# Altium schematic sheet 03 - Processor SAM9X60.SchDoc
size B; CompanyName: Microchip Technology Inc.; Organization: Microchip Technology; Address1: 2355 West Chandler Blvd.; Address2: Chandler, AZ  85224; Address4: USA; DocumentNumber: 3; SheetNumber: 3; SheetTotal: 13; SheetTitle: Processor SAM9X60
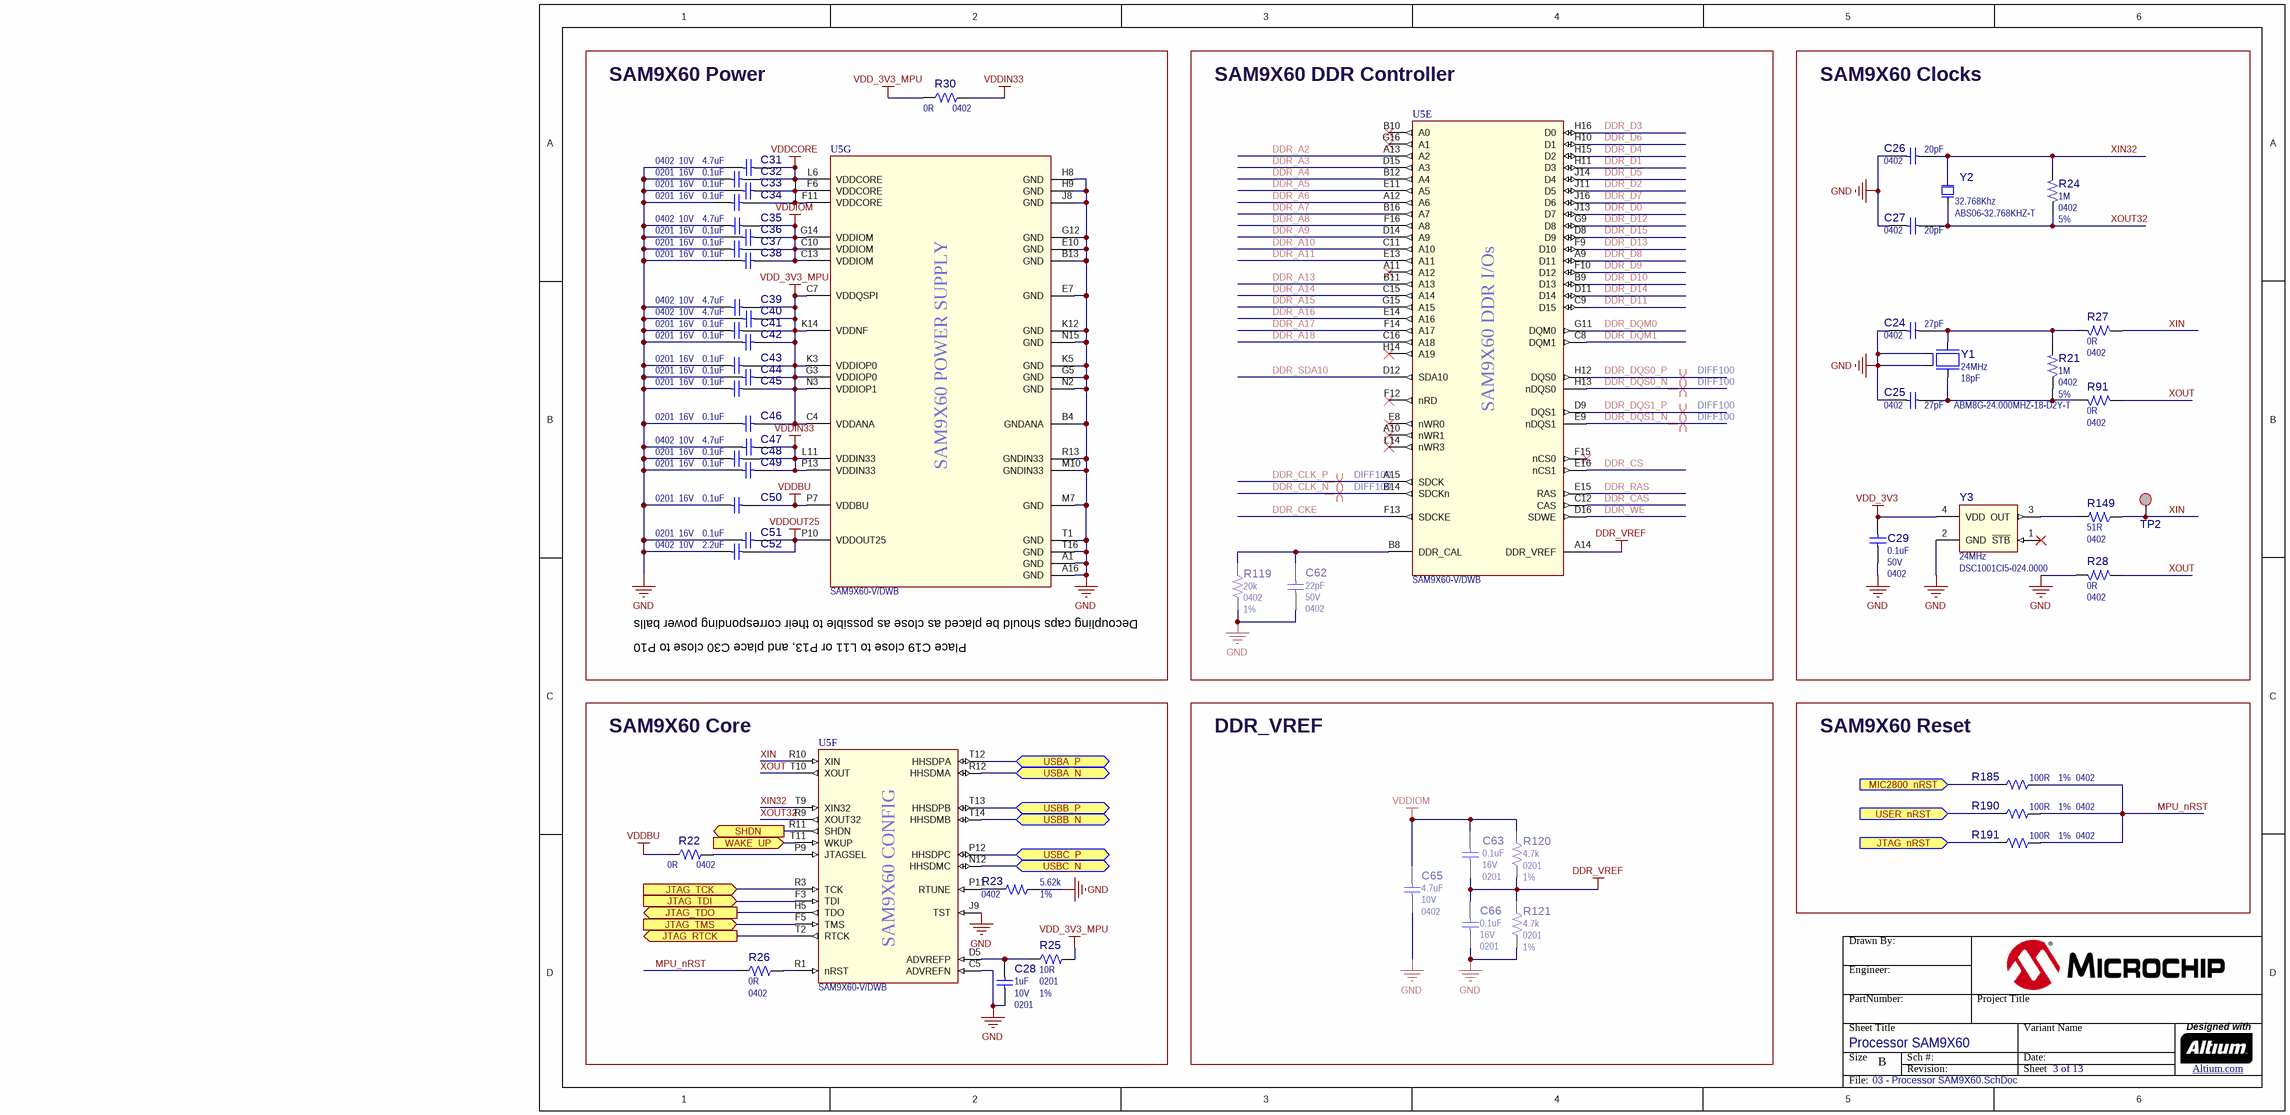
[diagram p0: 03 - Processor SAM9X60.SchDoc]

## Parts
?  (no value)  (graphical)
C24  value 27pF  Package: 0402  [CAP_C_0402]  (hidden comment: Capacitor NP)
C25  value 27pF  Package: 0402  [CAP_C_0402]  (hidden comment: Capacitor NP)
C26  value 20pF  Package: 0402  [CAP_C_0402]  (hidden comment: Capacitor NP)
C27  value 20pF  Package: 0402  [CAP_C_0402]  (hidden comment: Capacitor NP)
C28  value 1uF  Voltage: 10V  Package: 0201  [CAP_C_0201]  (hidden comment: Capacitor NP)
C29  value 0.1uF  Voltage: 50V  Package: 0402  [CAP_C_0402]  (hidden comment: Capacitor NP)
C31  value 4.7uF  Voltage: 10V  Package: 0402  [CAP_C_0402]  (hidden comment: Capacitor NP)
C32  value 0.1uF  Voltage: 16V  Package: 0201  [CAP_C_0201]  (hidden comment: Capacitor NP)
C33  value 0.1uF  Voltage: 16V  Package: 0201  [CAP_C_0201]  (hidden comment: Capacitor NP)
C34  value 0.1uF  Voltage: 16V  Package: 0201  [CAP_C_0201]  (hidden comment: Capacitor NP)
C35  value 4.7uF  Voltage: 10V  Package: 0402  [CAP_C_0402]  (hidden comment: Capacitor NP)
C36  value 0.1uF  Voltage: 16V  Package: 0201  [CAP_C_0201]  (hidden comment: Capacitor NP)
C37  value 0.1uF  Voltage: 16V  Package: 0201  [CAP_C_0201]  (hidden comment: Capacitor NP)
C38  value 0.1uF  Voltage: 16V  Package: 0201  [CAP_C_0201]  (hidden comment: Capacitor NP)
C39  value 4.7uF  Voltage: 10V  Package: 0402  [CAP_C_0402]  (hidden comment: Capacitor NP)
C40  value 4.7uF  Voltage: 10V  Package: 0402  [CAP_C_0402]  (hidden comment: Capacitor NP)
C41  value 0.1uF  Voltage: 16V  Package: 0201  [CAP_C_0201]  (hidden comment: Capacitor NP)
C42  value 0.1uF  Voltage: 16V  Package: 0201  [CAP_C_0201]  (hidden comment: Capacitor NP)
C43  value 0.1uF  Voltage: 16V  Package: 0201  [CAP_C_0201]  (hidden comment: Capacitor NP)
C44  value 0.1uF  Voltage: 16V  Package: 0201  [CAP_C_0201]  (hidden comment: Capacitor NP)
C45  value 0.1uF  Voltage: 16V  Package: 0201  [CAP_C_0201]  (hidden comment: Capacitor NP)
C46  value 0.1uF  Voltage: 16V  Package: 0201  [CAP_C_0201]  (hidden comment: Capacitor NP)
C47  value 4.7uF  Voltage: 10V  Package: 0402  [CAP_C_0402]  (hidden comment: Capacitor NP)
C48  value 0.1uF  Voltage: 16V  Package: 0201  [CAP_C_0201]  (hidden comment: Capacitor NP)
C49  value 0.1uF  Voltage: 16V  Package: 0201  [CAP_C_0201]  (hidden comment: Capacitor NP)
C50  value 0.1uF  Voltage: 16V  Package: 0201  [CAP_C_0201]  (hidden comment: Capacitor NP)
C51  value 0.1uF  Voltage: 16V  Package: 0201  [CAP_C_0201]  (hidden comment: Capacitor NP)
C52  value 2.2uF  Voltage: 10V  Package: 0402  [CAP_C_0402]  (hidden comment: Capacitor NP)
C62  value 22pF  Voltage: 50V  Package: 0402  [CAP_C_0402]  (hidden comment: Capacitor NP)
C63  value 0.1uF  Voltage: 16V  Package: 0201  [CAP_C_0201]  (hidden comment: Capacitor NP)
C65  value 4.7uF  Voltage: 10V  Package: 0402  [CAP_C_0402]  (hidden comment: Capacitor NP)
C66  value 0.1uF  Voltage: 16V  Package: 0201  [CAP_C_0201]  (hidden comment: Capacitor NP)
R21  value 1M  Package: 0402  Tolerance: 5%  [RES_C_0402]  (hidden comment: Resistor)
R22  value 0R  Package: 0402  [RES_C_0402]  (hidden comment: Resistor)
R23  value 5.62k  Package: 0402  Tolerance: 1%  [RES_C_0402]  (hidden comment: Resistor)
R24  value 1M  Package: 0402  Tolerance: 5%  [RES_C_0402]  (hidden comment: Resistor)
R25  value 10R  Package: 0201  Tolerance: 1%  [RES_C_0201]  (hidden comment: Resistor)
R26  value 0R  Package: 0402  [RES_C_0402]  (hidden comment: Resistor)
R27  value 0R  Package: 0402  [RES_C_0402]  (hidden comment: Resistor)
R28  value 0R  Package: 0402  [RES_C_0402]  (hidden comment: Resistor)
R30  value 0R  Package: 0402  [RES_C_0402]  (hidden comment: Resistor)
R91  value 0R  Package: 0402  [RES_C_0402]  (hidden comment: Resistor)
R119  value 20k  Package: 0402  Tolerance: 1%  [RES_C_0402]  (hidden comment: Resistor)
R120  value 4.7k  Package: 0201  Tolerance: 1%  [RES_C_0201]  (hidden comment: Resistor)
R121  value 4.7k  Package: 0201  Tolerance: 1%  [RES_C_0201]  (hidden comment: Resistor)
R149  value 51R  Package: 0402  [RES_C_0402]  (hidden comment: Resistor)
R185  value 100R  Package: 0402  Tolerance: 1%  [RES_C_0402]  (hidden comment: Resistor)
R190  value 100R  Package: 0402  Tolerance: 1%  [RES_C_0402]  (hidden comment: Resistor)
R191  value 100R  Package: 0402  Tolerance: 1%  [RES_C_0402]  (hidden comment: Resistor)
TP2  SMD Test Point  [TP_1x1_SMD]  (value not drawn)  (no BOM)
U5  value SAM9X60-V/DWB  [SAM9X60 TFBGA-228]  (hidden comment: SAM9X60 TFBGA-228)  (parts E,F,G of 7)
Y1  value 24MHz  Load Capacitance: 18pF  Manufacturer Part Number 1: ABM8G-24.000MHZ-18-D2Y-T  [CRYSTAL_ABM8G]  (hidden comment: Crystal 4 Pins)
Y2  value 32.768Khz  Manufacturer Part Number 1: ABS06-32.768KHZ-T  [CRYSTAL_ABS06]  (hidden comment: Crystal 2 Pins)
Y3  value 24MHz  Manufacturer Part Number 1: DSC1001CI5-024.0000  [CDFN-4_3.2X2.5]  (hidden comment: DSC10xx DFN-4)

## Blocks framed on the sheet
SAM9X60 Power: C31-C52 R30 U5
SAM9X60 DDR Controller: C62 R119 U5
SAM9X60 Clocks: C24-C27 C29 R21 R24 R27 R28 R91 R149 TP2 Y1-Y3
SAM9X60 Core: C28 R22 R23 R25 R26 U5
DDR_VREF: C63 C65 C66 R120 R121
SAM9X60 Reset: R185 R190 R191

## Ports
JTAG_nRST (in), JTAG_RTCK (out), JTAG_TCK (in), JTAG_TDI (in), JTAG_TDO (out), JTAG_TMS (in), MIC2800_nRST (in), SHDN (out), USBA_N (bidir), USBA_P (bidir), USBB_N (bidir), USBB_P (bidir), USBC_N (bidir), USBC_P (bidir), USER_nRST (in), WAKE_UP (in)

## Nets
DDR_VREF: C63.1 C66.2 R120.1 R121.2 U5.A14(DDR_VREF)
GND: C24.2 C25.2 C26.2 C27.2 C28.1 C29.1 C31.1 C32.2 C33.2 C34.2 C35.1 C36.2 C37.2 C38.2 C39.1 C40.1 C41.2 C42.2 C43.2 C44.2 C45.2 C46.2 C47.1 C48.2 C49.2 C50.2 C51.2 C52.2 C62.1 C65.1 C66.1 R23.1 R28.2 R119.1 R121.1 U5.A1(GND) U5.A16(GND) U5.B4(GNDANA) U5.B13(GND) U5.C5(ADVREFN) U5.E7(GND) U5.E10(GND) U5.G5(GND) U5.G12(GND) U5.H8(GND) U5.H9(GND) U5.J8(GND) U5.J9(TST) U5.K5(GND) U5.K12(GND) U5.M7(GND) U5.M10(GNDIN33) U5.N2(GND) U5.N15(GND) U5.R13(GNDIN33) U5.T1(GND) U5.T16(GND) Y1.2(GND) Y1.4(GND) Y3.2(GND)
VDD_3V3: C29.2 Y3.4(VDD)
VDD_3V3_MPU: C39.2 C40.2 C41.1 C42.1 C43.1 C44.1 C45.1 C46.1 R25.2 R30.1 U5.C4(VDDANA) U5.C7(VDDQSPI) U5.G3(VDDIOP0) U5.K3(VDDIOP0) U5.K14(VDDNF) U5.N3(VDDIOP1)
VDDBU: C50.1 R22.1 U5.P7(VDDBU)
VDDCORE: C31.2 C32.1 C33.1 C34.1 U5.F6(VDDCORE) U5.F11(VDDCORE) U5.L6(VDDCORE)
VDDIN33: C47.2 C48.1 C49.1 R30.2 U5.L11(VDDIN33) U5.P13(VDDIN33)
VDDIOM: C35.2 C36.1 C37.1 C38.1 C63.2 C65.2 R120.2 U5.C10(VDDIOM) U5.C13(VDDIOM) U5.G14(VDDIOM)
VDDOUT25: C51.1 C52.1 U5.P10(VDDOUT25)
DDR_A2: U5.A13(A2)
DDR_A3: U5.D15(A3)
DDR_A4: U5.B12(A4)
DDR_A5: U5.E11(A5)
DDR_A6: U5.A12(A6)
DDR_A7: U5.B16(A7)
DDR_A8: U5.F16(A8)
DDR_A9: U5.D14(A9)
DDR_A10: U5.C11(A10)
DDR_A11: U5.E13(A11)
DDR_A13: U5.B11(A13)
DDR_A14: U5.C15(A14)
DDR_A15: U5.G15(A15)
DDR_A16: U5.E14(A16)
DDR_A17: U5.F14(A17)
DDR_A18: U5.C16(A18)
DDR_CAS: U5.C12(CAS)
DDR_CKE: U5.F13(SDCKE)
DDR_CLK_N: U5.B14(SDCKn)
DDR_CLK_P: U5.A15(SDCK)
DDR_CS: U5.E16(nCS1)
DDR_D0: U5.J13(D7)
DDR_D1: U5.H11(D3)
DDR_D2: U5.J11(D5)
DDR_D3: U5.H16(D0)
DDR_D4: U5.H15(D2)
DDR_D5: U5.J14(D4)
DDR_D6: U5.H10(D1)
DDR_D7: U5.J16(D6)
DDR_D8: U5.A9(D11)
DDR_D9: U5.F10(D12)
DDR_D10: U5.B9(D13)
DDR_D11: U5.C9(D15)
DDR_D12: U5.G9(D8)
DDR_D13: U5.F9(D10)
DDR_D14: U5.D11(D14)
DDR_D15: U5.D8(D9)
DDR_DQM0: U5.G11(DQM0)
DDR_DQM1: U5.C8(DQM1)
DDR_DQS0_N: U5.H13(nDQS0)
DDR_DQS0_P: U5.H12(DQS0)
DDR_DQS1_N: U5.E9(nDQS1)
DDR_DQS1_P: U5.D9(DQS1)
DDR_RAS: U5.E15(RAS)
DDR_SDA10: U5.D12(SDA10)
DDR_WE: U5.D16(SDWE)
JTAG_nRST: R191.1 ; port JTAG_nRST
JTAG_RTCK: U5.T2(RTCK) ; port JTAG_RTCK
JTAG_TCK: U5.R3(TCK) ; port JTAG_TCK
JTAG_TDI: U5.F3(TDI) ; port JTAG_TDI
JTAG_TDO: U5.H5(TDO) ; port JTAG_TDO
JTAG_TMS: U5.F5(TMS) ; port JTAG_TMS
MIC2800_nRST: R185.1 ; port MIC2800_nRST
MPU_nRST: R26.1 R185.2 R190.2 R191.2
SHDN: U5.R11(SHDN) ; port SHDN
USBA_N: U5.R12(HHSDMA) ; port USBA_N
USBA_P: U5.T12(HHSDPA) ; port USBA_P
USBB_N: U5.T14(HHSDMB) ; port USBB_N
USBB_P: U5.T13(HHSDPB) ; port USBB_P
USBC_N: U5.N12(HHSDMC) ; port USBC_N
USBC_P: U5.P12(HHSDPC) ; port USBC_P
USER_nRST: R190.1 ; port USER_nRST
WAKE_UP: U5.T11(WKUP) ; port WAKE_UP
XIN: R27.1 R149.1 TP2.1 U5.R10(XIN)
XIN32: C26.1 R24.2 U5.T9(XIN32) Y2.2(Osc2)
XOUT: R28.1 R91.1 U5.T10(XOUT)
XOUT32: C27.1 R24.1 U5.R9(XOUT32) Y2.1(Osc1)
NetC24_1: C24.1 R21.2 R27.2 Y1.1(Osc1)
NetC25_1: C25.1 R21.1 R91.2 Y1.3(Osc2)
NetC28_2: C28.2 R25.1 U5.D5(ADVREFP)
NetC62_2: C62.2 R119.2 U5.B8(DDR_CAL)
NetR22_2: R22.2 U5.P9(JTAGSEL)
NetR23_2: R23.2 U5.P11(RTUNE)
NetR26_2: R26.2 U5.R1(nRST)
NetR149_2: R149.2 Y3.3(OUT)

Not connected (* = marked no-connect by the designer): U5 A10(nWR1)* A11(A12)* B10(A0)* E8(nWR0)* F12(nRD)* F15(nCS0)* G16(A1)* H14(A19)* L14(nWR3)*; Y3 1(~{STB})*

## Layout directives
differential pair; differential pair class DIFF100; net class DIFF100; rule Matched Net Lengths [Tolerance = 10mil]: DDR_CLK_N, DDR_CLK_P, DDR_DQS0_N, DDR_DQS0_P, DDR_DQS1_N, DDR_DQS1_P

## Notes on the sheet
- (near U5) SAM9X60 DDR I/Os
- (near U5) SAM9X60 POWER SUPPLY
- Decoupling caps should be placed as close as possible to their corresponding power balls
- Place C19 close to L11 or P13, and place C30 close to P10
- (near U5) SAM9X60 CONFIG

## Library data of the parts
? = Title Block B
C24 C25 = CAP0349: Capacitor; Manufacturer 1: Murata; Manufacturer Part Number 1: GRM1555C1H270JA01D; Voltage: 50V; Description_: CAP CER 27pF 50V 5% NP0 SMD 0402; Dev Tools Status: Production; Tolerance: 5%; Temperature Coeffcient: NP0; Type: Ceramic; Populated: DNP
C26 C27 = CAP0364: Capacitor; Manufacturer 1: Murata; Manufacturer Part Number 1: GRM1555C1H200JZ01D; Voltage: 50V; Description_: CAP CER 20pF 50V 5% C0G SMD 0402; Dev Tools Status: Production; Tolerance: 5%; Temperature Coeffcient: C0G; Type: Ceramic; Populated: DNP
C28 = CAP2024: Capacitor; Manufacturer 1: Murata Electronics North America; Manufacturer Part Number 1: GRM033R61A105ME15D; Description_: CAP CER 1uF 10V 20% X5R SMD 0201; Dev Tools Status: Design; Tolerance: 20%; Temperature Coeffcient: X5R; Type: Ceramic; Owner: Ilie Galan; Populated: YES
C29 = CAP1463: Capacitor; Manufacturer 1: TDK Corporation; Manufacturer Part Number 1: C1005X7R1H104K050BB; Description_: CAP CER 0.1uF 50V 10% X7R SMD 0402; Dev Tools Status: Production; Tolerance: 10%; Temperature Coeffcient: X7R; Type: Ceramic; Owner: Jamus Griego; Populated: YES
C31 C35 C39 C40 C47 C65 = CAP1684: Capacitor; Manufacturer 1: TDK Corporation; Manufacturer Part Number 1: C1005X5R1A475K050BC; Description_: CAP CER 4.7uF 10V 10% X5R SMD 0402; Dev Tools Status: Production; Tolerance: 10%; Temperature Coeffcient: X5R; Type: Ceramic; Owner: Jesus Aviles; Populated: YES
C32-C34 C36-C38 C41-C46 C48-C51 C63 C66 = CAP1203: Capacitor; Manufacturer 1: Murata; Manufacturer Part Number 1: GRM033R61C104KE84D; Description_: CAP CER 0.1uF 16V 10% X5R SMD 0201; Dev Tools Status: Production; Tolerance: 10%; Temperature Coeffcient: X5R; Type: Ceramic; Owner: Tad Ahlvers; Populated: YES
C52 = CAP1468: Capacitor; Manufacturer 1: TDK Corporation; Manufacturer Part Number 1: C1005X7S1A225K050BC; Description_: CAP CER 2.2uF 10V 10% X7S SMD 0402; Dev Tools Status: Production; Tolerance: 10%; Temperature Coeffcient: X7S; Type: Ceramic; Owner: Sorin Stanoaia; Populated: YES
C62 = CAP1042: Capacitor; Manufacturer 1: Murata; Manufacturer Part Number 1: GRM1555C1H220JZ01D; Description_: CAP CER 22pF 50V 5% NP0 SMD 0402; Dev Tools Status: Production; Tolerance: 5%; Temperature Coeffcient: NP0; Type: Ceramic; Owner: Sompoch Loboonlert; Populated: Yes
R21 R24 = RES1019: Manufacturer 1: Yageo; Manufacturer Part Number 1: RC0402JR-071ML; Description_: RES TKF 1M 5% 1/16W SMD 0402; Dev Tools Status: Production; Voltage: 50V; Temperature Coeffcient: 100ppm/C; Power: 1/16W; Owner: Tad Ahlvers; Populated: DNP
R22 R27 R91 = RSMT1040: Manufacturer 1: Yageo; Manufacturer Part Number 1: RC0402JR-070RL; Description_: RES TKF 0R 1/16W SMD 0402; Dev Tools Status: Production; Power: 1/16W; Owner: Sompoch Loboonlert; Populated: DNP
R23 = RES1505: Manufacturer 1: Vishay Dale; Manufacturer Part Number 1: CRCW04025K62FKED; Description_: RES TKF 5.62k 1% 1/16W SMD 0402; Dev Tools Status: Production; Voltage: 50V; Temperature Coeffcient: 100ppm/C; Power: 1/16W; Owner: Mike Ragsdale; Populated: YES
R25 = RES2180: Manufacturer 1: Vishay Dale; Manufacturer Part Number 1: CRCW020110R0FNED; Description_: RES TKF 10R 1% 1/20W SMD 0201; Dev Tools Status: Design; Temperature Coeffcient: 200ppm/C; Power: 1/20W; Owner: Ilie Galan; Populated: YES
R26 R28 R30 = RSMT1040: Manufacturer 1: Yageo; Manufacturer Part Number 1: RC0402JR-070RL; Description_: RES TKF 0R 1/16W SMD 0402; Dev Tools Status: Production; Power: 1/16W; Owner: Sompoch Loboonlert; Populated: Yes
R119 = RSMT1238: Manufacturer 1: Yageo; Manufacturer Part Number 1: RC0402FR-0720KL; Description_: RES TKF 20K 1% 1/16W SMD 0402; Dev Tools Status: Design; Voltage: 100V; Temperature Coeffcient: 100ppm/C; Current: 1A; Power: 1/16; Owner: Dragos Danaila; Populated: YES
R120 R121 = RES1519: Manufacturer 1: Panasonic Electronic Components; Manufacturer Part Number 1: ERJ-1GEF4701C; Description_: RES TKF 4.7k 1% 1/20W SMD 0201; Dev Tools Status: Design; Voltage: 25V; Temperature Coeffcient: 200ppm/C; Power: 1/20W; Owner: Gabor Bihari; Populated: YES
R149 = RSMT1243: Manufacturer 1: Yageo; Manufacturer Part Number 1: RC0402FR-0751RL; Tolerance: 1%; Description_: RES TKF 51R 1% 1/16W SMD 0402; Dev Tools Status: Design; Voltage: 100V; Temperature Coeffcient: 100ppm/C; Current: 1A; Power: 1/16W; Owner: Ciprian Abramov; Populated: YES
R185 R190 R191 = RES1587: Manufacturer 1: Yageo; Manufacturer Part Number 1: RC0402FR-07100RL; Description_: RES TKF 100R 1% 1/16W SMD 0402; Dev Tools Status: Design; Voltage: 50V; Temperature Coeffcient: 100ppm/C; Power: 1/16W; Owner: Sorin Stanoaia; Populated: YES
TP2 = TEST-POINT: Test Point pad 1.00mm
U5 = MIC8772: SAM9X60 MPU 600MHz ARM926EJ-S TFBGA-228; Manufacturer 1: Microchip; Description_: MCHP MCU 32-BIT 600 MHz 64kB  SAM9X60-V/DWB TFBGA228; Populated: YES; MAPS Description: ARM926 MPU, BGA, IND TEMP; Dev Tools Status: Design; Owner: Ilie Galan; MPC: STU029DWBR01; LeadContent: Pb-FREE; TempRange: Various; Stage: NREL; PackageWidth: 11x11x1.2mm; PackingMedia: TRAY; ForceMinOrderQtyMult: True; MinOrderQty: 176; LeadCount: 228; Program Memory KBytes: 0; Ram: 69584; IOPins: 112; MaxSpeed: 600; OscillatorMHz: 32kHz, 12MHz; ADC Channels: 12; USART: 13; SPI: 6; CAN: 2; USBChannels: 3; DigitalTimerQty_32bit: 8
Y1 = OSC1047: Crystal; Manufacturer 1: Abracon Corporation; Description_: CRYSTAL 24MHz 18pF SMD ABM8G; Dev Tools Status: Production; Owner: Mark Loper; Populated: DNP
Y2 = OSC1063: Crystal; Manufacturer 1: Abracon LLC; Description_: CRYSTAL 32.768kHz 12.5pF SMD ABS06; Dev Tools Status: Design; Owner: Jamus Griego; Populated: DNP
Y3 = MIC7861: Manufacturer 1: Microchip Technology; Description_: MCHP CLOCK OSCILLATOR 24MHz DSC1001CI5-024.0000 DFN-4; Dev Tools Status: Design; Owner: Ilie Galan; Populated: YES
